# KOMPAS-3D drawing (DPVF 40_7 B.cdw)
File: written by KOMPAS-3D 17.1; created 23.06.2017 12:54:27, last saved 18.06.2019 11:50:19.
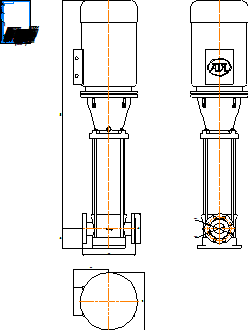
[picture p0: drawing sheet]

Sheet 1: A4, portrait

Title block, sheet 1: name: DPVF 40_7 B; material: Внимание! Данный продукт является объектом авторского права ООО «Торговый Дом АДЛ». / Запрещается изменение, копирование, распространение / (в том числе путем копирования на другие сайты и ресурсы в Интернете) / или любое иное использование информации и объектов без предварительного / согласия правообладателя (ООО «Торговый Дом АДЛ»).; scale: 1:1; sheets: 1; organisation: ООО "Торговый дом АДЛ"; sheet format: A4; stored path: C:\Клочков АВ\Насосы\DP PAMS\DPVF 40\Компас 2d\DPVF 40_7 B.cdw

Views: Спереди 1
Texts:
  Клочков АВ
  ООО АДЛ ГРУПП
Dimensions and other numbers on the sheet: 365; 250; 400; 209,6; 1585,5; 140; 168,1; 76,2; 1:1; 1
